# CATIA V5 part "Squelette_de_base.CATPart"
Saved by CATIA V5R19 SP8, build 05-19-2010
Part number: squelette_de_base
Publications: "Point.1", "Point.2", "Point.3", "Point.4", "Point.6", "Point.8", "Point.9", "Point.10", "Point.11", "Point.12_biellete_a", "Point.13_biellete_a", "Point.14_biellete_a", "Point.15_biellete_a", "Point.17", "Point.18", "Point.19_amortisseur", "Point.20_amortisseur", "Point.21_début_ressort", "Point.22_barre_liaison", "Point.23_barre_liaison_2"
Bounding box of the stored display mesh (mm): x -40 to 200, y -800 to 0, z -144 to 475
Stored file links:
  C:\Users\Pauline\Desktop\CFAO_Catia\Compte_rendu\pmayet_assemblage_animation4\Squelette_de_base.CATPart
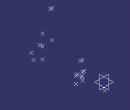
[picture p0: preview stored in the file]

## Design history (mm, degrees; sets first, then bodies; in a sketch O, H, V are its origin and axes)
Set1
  Point1: (0, -800, 0)
  Point2: (0, -770, 0)
  Point3: (0, 0, 140), relative to Point2
  Point4: (0, 0, -140), relative to Point2
  Point5: (0, -294, 80)
  Point6: (40, -294, -48)
  Point7: (-40, -294, -48)
  Point8: (55, -294, -144)
  Point9: (55, -294, -48)
  Point10 "Point.12_biellete_a": (-23, -294, 80)
  Point11 "Point.13_biellete_a": (-23, -294, -48)
  Point12 "Point.14_biellete_a": (-23, -294, -96)
  Point13 "Point.15_biellete_a": (-23, -294, -144)
  Point14: (140, -770, 0)
  Point15: (200, -680, 0)
  Point16 "Point.19_amortisseur": type Between, FirstPoint Point3, SecondPoint Point5, Ratio 0.25
  Point17 "Point.20_amortisseur": (0, 0, 350), relative to Point16
  Point18 "Point.21_début_ressort": (0, -20, 330), relative to Point16
  Point19 "Point.22_barre_liaison": (-10, -294, -96)
  Point20 "Point.23_barre_liaison_2": (-10, 0, -96)
Body1 (main body)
